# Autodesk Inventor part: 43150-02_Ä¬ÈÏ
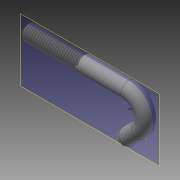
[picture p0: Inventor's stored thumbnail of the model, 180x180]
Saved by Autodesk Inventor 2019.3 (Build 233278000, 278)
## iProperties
Created: 2010-06
Part Number: 43150-02_Ä¬ÈÏ
Material: Ogólny
Document SubType Name: Modeling
Designer: CADENGINEERING4
Density: 1 g/cm^3
Appearance: Domyślna
Author: CADENGINEERING4
Revision Number: ÈÎºÎ
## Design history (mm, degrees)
feature "NONE"
node "Bryła1"
